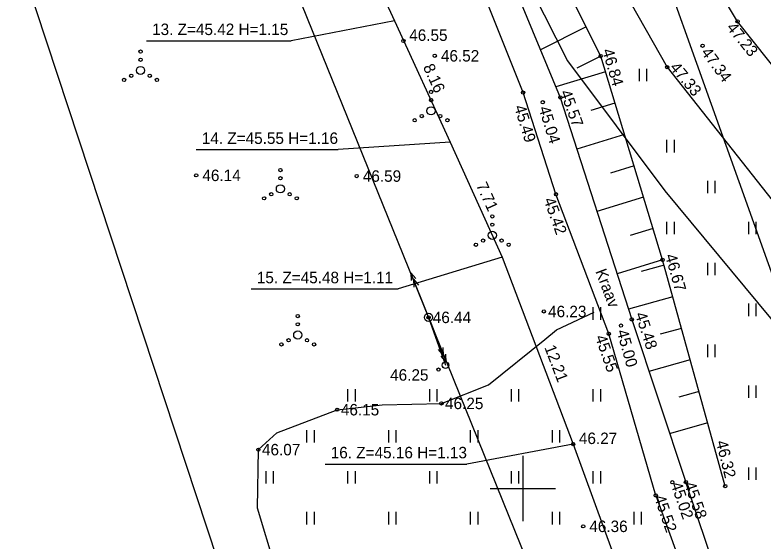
# Model space of a CAD drawing. Extents: x 642747 to 644424, y 6457048 to 6458238.
# Drawn here: x 644068.96 to 644114.68, y 6457646.79 to 6457678.92 of the extents above; entities that cross this region are included whole.
import ezdxf

# ---------------------------------------------------------------- set-up
doc = ezdxf.new("R2010")
doc.units = 0
for name, color, linetype in [('HALJASTUS', 7, 'Continuous'), ('JOONSIDE', 7, 'Continuous'), ('KOORDPUNKT', 7, 'Continuous'), ('KORGUS', 7, 'Continuous'), ('KPKAABEL', 7, 'Continuous'), ('KPOHULIIN', 7, 'Continuous'), ('MOOTPIIR', 7, 'Continuous'), ('PIIR', 7, 'Continuous'), ('POST', 7, 'Continuous'), ('RELJEEF', 7, 'Continuous'), ('TEE', 7, 'Continuous'), ('VEEKOGU', 7, 'Continuous'), ('VORK', 7, 'Continuous')]:
    doc.layers.add(name, color=color, linetype=linetype)

msp = doc.modelspace()

# ---------------------------------------------------------------- linework, layer by layer
at = {"layer": 'HALJASTUS'}
for p, q in [((644107.111, 6457675.634), (644107.111, 6457674.873)), ((644107.566, 6457675.634), (644107.566, 6457674.873)), ((644108.79, 6457671.289), (644108.79, 6457670.528)), ((644109.245, 6457671.289), (644109.245, 6457670.528)), ((644111.29, 6457668.789), (644111.29, 6457668.028)), ((644111.745, 6457668.789), (644111.745, 6457668.028)), ((644108.79, 6457666.289), (644108.79, 6457665.528)), ((644109.245, 6457666.289), (644109.245, 6457665.528)), ((644113.79, 6457666.289), (644113.79, 6457665.528)), ((644114.245, 6457666.289), (644114.245, 6457665.528)), ((644111.29, 6457663.789), (644111.29, 6457663.028)), ((644111.745, 6457663.789), (644111.745, 6457663.028)), ((644113.79, 6457661.289), (644113.79, 6457660.528)), ((644114.245, 6457661.289), (644114.245, 6457660.528)), ((644104.29, 6457661.069), (644104.29, 6457660.307)), ((644104.745, 6457661.069), (644104.745, 6457660.307)), ((644111.29, 6457658.789), (644111.29, 6457658.028)), ((644111.745, 6457658.789), (644111.745, 6457658.028)), ((644113.79, 6457656.289), (644113.79, 6457655.528)), ((644114.245, 6457656.289), (644114.245, 6457655.528)), ((644089.29, 6457656.069), (644089.29, 6457655.307)), ((644089.745, 6457656.069), (644089.745, 6457655.307)), ((644094.29, 6457656.069), (644094.29, 6457655.307)), ((644094.745, 6457656.069), (644094.745, 6457655.307)), ((644099.29, 6457656.069), (644099.29, 6457655.307)), ((644099.745, 6457656.069), (644099.745, 6457655.307)), ((644104.29, 6457656.069), (644104.29, 6457655.307)), ((644104.745, 6457656.069), (644104.745, 6457655.307)), ((644086.79, 6457653.569), (644086.79, 6457652.807)), ((644087.245, 6457653.569), (644087.245, 6457652.807)), ((644091.79, 6457653.569), (644091.79, 6457652.807)), ((644092.245, 6457653.569), (644092.245, 6457652.807)), ((644096.79, 6457653.569), (644096.79, 6457652.807)), ((644097.245, 6457653.569), (644097.245, 6457652.807)), ((644101.79, 6457653.569), (644101.79, 6457652.807)), ((644102.245, 6457653.569), (644102.245, 6457652.807)), ((644084.29, 6457651.069), (644084.29, 6457650.307)), ((644084.745, 6457651.069), (644084.745, 6457650.307)), ((644089.29, 6457651.069), (644089.29, 6457650.307)), ((644089.745, 6457651.069), (644089.745, 6457650.307)), ((644094.29, 6457651.069), (644094.29, 6457650.307)), ((644094.745, 6457651.069), (644094.745, 6457650.307)), ((644099.29, 6457651.069), (644099.29, 6457650.307)), ((644099.745, 6457651.069), (644099.745, 6457650.307)), ((644104.29, 6457651.069), (644104.29, 6457650.307)), ((644104.745, 6457651.069), (644104.745, 6457650.307)), ((644113.79, 6457651.289), (644113.79, 6457650.528)), ((644114.245, 6457651.289), (644114.245, 6457650.528)), ((644086.79, 6457648.569), (644086.79, 6457647.807)), ((644087.245, 6457648.569), (644087.245, 6457647.807)), ((644091.79, 6457648.569), (644091.79, 6457647.807)), ((644092.245, 6457648.569), (644092.245, 6457647.807)), ((644096.79, 6457648.569), (644096.79, 6457647.807)), ((644097.245, 6457648.569), (644097.245, 6457647.807)), ((644101.79, 6457648.569), (644101.79, 6457647.807)), ((644102.245, 6457648.569), (644102.245, 6457647.807)), ((644106.79, 6457648.569), (644106.79, 6457647.807)), ((644107.245, 6457648.569), (644107.245, 6457647.807))]:
    msp.add_line(p, q, dxfattribs=at)
msp.add_lwpolyline([(644093.59, 6457618.355), (644093.565, 6457618.519), (644091.325, 6457626.212), (644087.019, 6457638.046), (644083.789, 6457648.804), (644083.837, 6457652.374), (644084.977, 6457653.397), (644088.66, 6457654.814), (644091.405, 6457655.119), (644095.028, 6457655.197), (644097.913, 6457656.324), (644101.344, 6457659.091), (644102.065, 6457659.686), (644104.362, 6457660.778)], dxfattribs=at)
for centre, radius in [((644076.635, 6457676.682), 0.1), ((644076.635, 6457676.182), 0.1), ((644076.635, 6457675.532), 0.25), ((644076.07, 6457675.207), 0.1), ((644077.2, 6457675.207), 0.1), ((644075.635, 6457674.957), 0.1), ((644077.635, 6457674.957), 0.1), ((644094.392, 6457674.218), 0.1), ((644094.392, 6457673.718), 0.1), ((644094.392, 6457673.068), 0.25), ((644093.392, 6457672.493), 0.1), ((644093.827, 6457672.743), 0.1), ((644094.957, 6457672.743), 0.1), ((644095.392, 6457672.493), 0.1), ((644085.187, 6457669.448), 0.1), ((644085.187, 6457668.948), 0.1), ((644085.187, 6457668.298), 0.25), ((644084.622, 6457667.973), 0.1), ((644085.752, 6457667.973), 0.1), ((644084.187, 6457667.723), 0.1), ((644086.187, 6457667.723), 0.1), ((644098.138, 6457666.615), 0.1), ((644098.138, 6457666.115), 0.1), ((644098.138, 6457665.465), 0.25), ((644097.573, 6457665.14), 0.1), ((644098.703, 6457665.14), 0.1), ((644097.138, 6457664.89), 0.1), ((644099.138, 6457664.89), 0.1), ((644086.246, 6457660.527), 0.1), ((644086.246, 6457660.027), 0.1), ((644086.246, 6457659.377), 0.25), ((644085.246, 6457658.802), 0.1), ((644085.681, 6457659.052), 0.1), ((644086.811, 6457659.052), 0.1), ((644087.246, 6457658.802), 0.1)]:
    msp.add_circle(centre, radius, dxfattribs=at)
at = {"layer": 'KOORDPUNKT'}
for p, q in [((644092.153, 6457678.564), (644085.846, 6457677.343)), ((644076.992, 6457677.343), (644085.846, 6457677.343)), ((644095.564, 6457671.153), (644088.71, 6457670.694)), ((644080.03, 6457670.694), (644088.71, 6457670.694)), ((644098.741, 6457664.129), (644092.389, 6457662.185)), ((644083.395, 6457662.185), (644092.389, 6457662.185)), ((644103.079, 6457652.715), (644096.59, 6457651.494)), ((644087.911, 6457651.494), (644096.59, 6457651.494))]:
    msp.add_line(p, q, dxfattribs=at)
for points in [[(644092.153, 6457678.564), (644092.153, 6457678.564), (644092.153, 6457678.564)], [(644095.564, 6457671.153), (644095.564, 6457671.153), (644095.564, 6457671.153)], [(644098.741, 6457664.129), (644098.741, 6457664.129), (644098.741, 6457664.129)], [(644103.079, 6457652.715), (644103.079, 6457652.715), (644103.079, 6457652.715)]]:
    msp.add_lwpolyline(points, dxfattribs=at)
at = {"layer": 'KORGUS'}
for centre in [(644113.131, 6457678.523), (644092.708, 6457677.336), (644110.991, 6457677.041), (644094.621, 6457676.425), (644104.761, 6457676.406), (644108.831, 6457675.729), (644100.02, 6457674.182), (644102.294, 6457673.88), (644101.224, 6457673.589), (644080.041, 6457669.125), (644089.848, 6457669.082), (644102.028, 6457667.972), (644108.543, 6457663.96), (644101.286, 6457660.811), (644094.239, 6457660.452), (644106.657, 6457660.328), (644106.001, 6457659.948), (644105.251, 6457659.448), (644094.848, 6457657.26), (644095.028, 6457655.197), (644088.66, 6457654.814), (644083.837, 6457652.374), (644103.079, 6457652.715), (644109.139, 6457650.384), (644109.969, 6457650.392), (644112.377, 6457650.146), (644108.124, 6457649.581), (644103.691, 6457647.69)]:
    msp.add_circle(centre, 0.1, dxfattribs=at)
at = {"layer": 'KPKAABEL'}
msp.add_lwpolyline([(644063.341, 6457736.874), (644063.814, 6457738.243), (644064.085, 6457738.786), (644069.675, 6457740.685), (644070.251, 6457740.516), (644070.657, 6457739.804), (644071.702, 6457735.361), (644072.419, 6457732.308), (644073.692, 6457725.34), (644075.548, 6457720.26), (644079.636, 6457709.071), (644081.299, 6457704.816), (644084.417, 6457695.285), (644092.153, 6457678.564), (644095.564, 6457671.153), (644098.741, 6457664.129), (644103.079, 6457652.715), (644111.131, 6457630.665)], dxfattribs=at)
at = {"layer": 'KPOHULIIN'}
for p, q in [((644093.153, 6457663.181), (644093.18, 6457662.707)), ((644093.153, 6457663.181), (644093.458, 6457662.817)), ((644094.146, 6457660.684), (644093.153, 6457663.181)), ((644093.314, 6457662.775), (644093.619, 6457662.41)), ((644093.314, 6457662.775), (644093.342, 6457662.3)), ((644094.331, 6457660.219), (644095.325, 6457657.722)), ((644095.163, 6457658.129), (644094.858, 6457658.494)), ((644095.163, 6457658.129), (644095.136, 6457658.603)), ((644095.325, 6457657.722), (644095.02, 6457658.087)), ((644095.325, 6457657.722), (644095.298, 6457658.197))]:
    msp.add_line(p, q, dxfattribs=at)
msp.add_lwpolyline([(644061.981, 6457739.913), (644094.239, 6457660.452), (644124.342, 6457586.031), (644125.691, 6457582.672)], dxfattribs=at)
at = {"layer": 'MOOTPIIR'}
msp.add_lwpolyline([(643525.446, 6457467.559), (643537.447, 6457435.458), (643944.848, 6457628.51), (644046.626, 6457529.09), (644067.022, 6457529.09), (644138.408, 6457598.401), (644075.1, 6457775.215), (644046.02, 6457752.582), (644092.466, 6457611.94), (644070.657, 6457576.375), (644041.981, 6457570.717), (643942.223, 6457662.862)], close=True, dxfattribs=at)
at = {"layer": 'PIIR'}
msp.add_lwpolyline([(644056.78, 6457779.28), (644062.47, 6457766.56), (644060.34, 6457762.97), (644041.41, 6457742.89), (644054.5, 6457738.54), (644058.72, 6457740.17), (644055.31, 6457749.58), (644061, 6457751.62), (644060.21, 6457753.82), (644065.16, 6457760.36), (644069.76, 6457744.43), (644073.59, 6457731.16), (644087.56, 6457695.23), (644092.09, 6457697.08), (644102.74, 6457676.12), (644108.68, 6457668.18), (644119.21, 6457655.5), (644137.18, 6457639.57)], dxfattribs=at)
at = {"layer": 'POST'}
msp.add_line((644094.239, 6457660.452), (644095.271, 6457657.531), dxfattribs=at)
for centre, radius in [((644094.239, 6457660.452), 0.25), ((644094.239, 6457660.452), 0.0234), ((644095.271, 6457657.531), 0.2)]:
    msp.add_circle(centre, radius, dxfattribs=at)
at = {"layer": 'RELJEEF'}
for p, q in [((644103.864, 6457678.194), (644101.082, 6457676.799)), ((644104.761, 6457676.406), (644103.306, 6457675.677)), ((644105.054, 6457675.442), (644102.027, 6457674.522)), ((644105.635, 6457673.528), (644104.165, 6457673.081)), ((644106.217, 6457671.614), (644103.308, 6457670.73)), ((644106.798, 6457669.701), (644105.36, 6457669.264)), ((644107.38, 6457667.787), (644104.534, 6457666.922)), ((644107.961, 6457665.874), (644106.554, 6457665.446)), ((644108.543, 6457663.96), (644105.76, 6457663.114)), ((644108.633, 6457663.636), (644107.237, 6457663.249)), ((644109.168, 6457661.709), (644106.455, 6457660.956)), ((644109.703, 6457659.782), (644108.388, 6457659.417)), ((644110.237, 6457657.855), (644107.696, 6457657.15)), ((644110.772, 6457655.928), (644109.546, 6457655.587)), ((644111.307, 6457654.001), (644108.941, 6457653.344))]:
    msp.add_line(p, q, dxfattribs=at)
msp.add_lwpolyline([(644112.377, 6457650.146), (644108.543, 6457663.96), (644104.761, 6457676.406), (644098.75, 6457688.389)], dxfattribs=at)
at = {"layer": 'TEE'}
for points in [[(644061.722, 6457771.823), (644064.397, 6457766.262), (644069.452, 6457755.916), (644076.842, 6457739.337), (644084.183, 6457724.283), (644091.562, 6457708.571), (644100.441, 6457690.483), (644108.831, 6457675.729), (644120.122, 6457661.417), (644128.409, 6457653.611)], [(644123.504, 6457665.54), (644123.416, 6457665.621), (644113.131, 6457678.523), (644106.187, 6457690.082), (644107.056, 6457690.755), (644112.042, 6457693.41)]]:
    msp.add_lwpolyline(points, dxfattribs=at)
at = {"layer": 'VEEKOGU'}
for points in [[(644108.124, 6457649.581), (644105.251, 6457659.448), (644102.028, 6457667.972), (644100.02, 6457674.182), (644093.965, 6457689.322)], [(644097.313, 6457685.871), (644102.294, 6457673.88), (644106.657, 6457660.328), (644109.969, 6457650.392)], [(644131.098, 6457587.913), (644122.69, 6457611.242), (644117.767, 6457627.249), (644109.969, 6457650.392)], [(644108.124, 6457649.581), (644116.541, 6457626.349), (644121.438, 6457610.958), (644129.984, 6457586.833)]]:
    msp.add_lwpolyline(points, dxfattribs=at)
at = {"layer": 'VORK'}
for p, q in [((644100, 6457652), (644100, 6457648)), ((644098, 6457650), (644102, 6457650))]:
    msp.add_line(p, q, dxfattribs=at)

# ---------------------------------------------------------------- texts
at = {"layer": 'JOONSIDE'}
for s, rotation, p in [('8.16', 294.7148, (644093.886, 6457675.744)), ('7.71', 294.3375, (644097.135, 6457668.524)), ('12.21', 290.8098, (644101.312, 6457658.616))]:
    msp.add_text(s, height=0.7, rotation=rotation, dxfattribs=at).set_placement(p)
at = {"layer": 'KOORDPUNKT'}
for s, p in [('13. Z=45.42 H=1.15', (644077.342, 6457677.693)), ('14. Z=45.55 H=1.16', (644080.38, 6457671.044)), ('15. Z=45.48 H=1.11', (644083.745, 6457662.535)), ('16. Z=45.16 H=1.13', (644088.261, 6457651.844))]:
    msp.add_text(s, height=0.7, dxfattribs=at).set_placement(p)
at = {"layer": 'KORGUS'}
for s, p in [('46.55', (644093.058, 6457677.336)), ('46.52', (644094.996, 6457676.075)), ('46.14', (644080.416, 6457668.775)), ('46.59', (644090.223, 6457668.732)), (' 46.23', (644101.286, 6457660.461)), (' 46.44', (644094.239, 6457660.102)), (' 46.25', (644091.632, 6457656.585)), ('46.15', (644088.881, 6457654.464)), ('46.25', (644095.249, 6457654.847)), ('46.27', (644103.429, 6457652.715)), ('46.07', (644084.058, 6457652.024)), ('46.36', (644104.066, 6457647.34))]:
    msp.add_text(s, height=0.7, dxfattribs=at).set_placement(p)
for s, rotation, p in [(' 47.23', 308.9041, (644112.256, 6457678.333)), (' 46.84', 286.3611, (644104.774, 6457677.003)), (' 47.34', 306.483, (644110.709, 6457676.833)), (' 47.33', 309.6515, (644108.783, 6457675.892)), (' 45.57', 290.0028, (644102.18, 6457674.449)), ('45.49', 286.9649, (644099.467, 6457673.308)), (' 45.04', 286.9649, (644100.889, 6457673.486)), (' 45.42', 289.6908, (644101.181, 6457667.878)), (' 46.67', 285.8274, (644108.62, 6457664.474)), (' 45.48', 288.1986, (644106.771, 6457660.898)), (' 45.55', 289.0523, (644104.328, 6457659.496)), (' 45.00', 285.606, (644105.664, 6457659.853)), (' 46.32', 283.8734, (644111.742, 6457653.101)), ('45.02', 289.0523, (644109.03, 6457650.27)), ('45.58', 289.0523, (644109.86, 6457650.278)), ('45.52', 289.0523, (644108.015, 6457649.467))]:
    msp.add_text(s, height=0.7, rotation=rotation, dxfattribs=at).set_placement(p)
at = {"layer": 'VEEKOGU'}
msp.add_text('Kraav', height=0.7, rotation=290.7102, dxfattribs=at).set_placement((644104.425, 6457663.264))

doc.saveas('drawing.dxf')
